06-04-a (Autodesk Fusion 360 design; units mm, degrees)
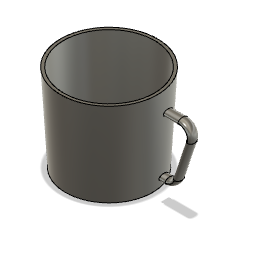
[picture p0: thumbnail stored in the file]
sketch "スケッチ1" plane through (0, 0, 0) normal (0, 0, 1) x axis (1, 0, 0)
  line L1 (0, 45) -> (0, 0)
  line L2 (-25, 45) -> (0, 45)
  line L3 (-22.5, 0) -> (-25, 45)
  line L4 (0, 0) -> (-22.5, 0)
  point P1 (0, 0)
  point P2 (0, 0)
  point P3 (0, 45)
  point P5 (-22.5, 0)
  coincident P1 P2
  vertical L1
  perpendicular L1 L2
  perpendicular L1 L4
  dimension "d1" = 50
  dimension "d2" distance P2 P3 = 45
  dimension "d3" distance L1 P5 = 45
revolve "回転" sketch "スケッチ1" AlongAngle 360
shell "シェル" innerThickness 1.5
offset_faces "面をオフセット" distance 1.5
sketch "スケッチ2" plane through (0, 0, 0) normal (0, 0, 1) x axis (1, 0, 0)
  line L1 (38.0629, 40) -> (24.7222, 40)
  line L2 (36.1396, 13.4189) -> (42.8063, 33.4189)
  line L3 (23.0556, 10) -> (31.3962, 10)
  line L4 (-22.5, 0) -> (-25, 45)
  line L5 (25, 45) -> (22.5, 0)
  line L6 (-22.5, 0) -> (22.5, 0)
  arc A1 centre (38.0629, 35) radius 5 clockwise from (38.0629, 40) to (42.8063, 33.4189)
  arc A2 centre (31.3962, 15) radius 5 clockwise from (36.1396, 13.4189) to (31.3962, 10)
  point P2 (24.7222, 40)
  point P5 (23.0556, 10)
  point P3 (45, 40)
  point P4 (35, 10)
  point P1 (0, 0)
  horizontal L1
  parallel L1 L3
  coincident P2 L5
  coincident P5 L5
  coincident P3 L1
  coincident P3 L2
  tangent L1 A1
  tangent L2 A1
  coincident P4 L2
  coincident P4 L3
  tangent L2 A2
  tangent L3 A2
  equal A1 A2
  dimension "d7" distance P1 P4 = 35
  dimension "d8" distance P1 P3 = 45
  dimension "d9" distance L3 L6 = 10
  dimension "d11" distance P3 P4 = 30
  dimension "d12" radius A1 = 5
work_plane "作業平面" PathDistance 0.1
sketch "スケッチ3" plane through (30.5693, 40, 0) normal (1, 0, 0) x axis (0, 1, 0)
  curve K1 (0, -2.5) -> (0, 2.5)
  curve K2 (1.5, 0) -> (-1.5, 0)
  closed curve K3 centre (0, 0)
  point P1 (0, 0)
  point P2 (0, 0)
  point P3 (0, 2.5)
  point P4 (0, -2.5)
  point P5 (-1.5, 0)
  point P6 (1.5, 0)
  coincident P1 P2
  vertical K1
  coincident K3 P3
  coincident K3 P4
  coincident K3 P5
  coincident K3 P6
  dimension "d14" = 3
  dimension "d15" distance K3 = 5
sweep "スイープ" sketch "スケッチ3" TwistAngle 0 TaperAngle 0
